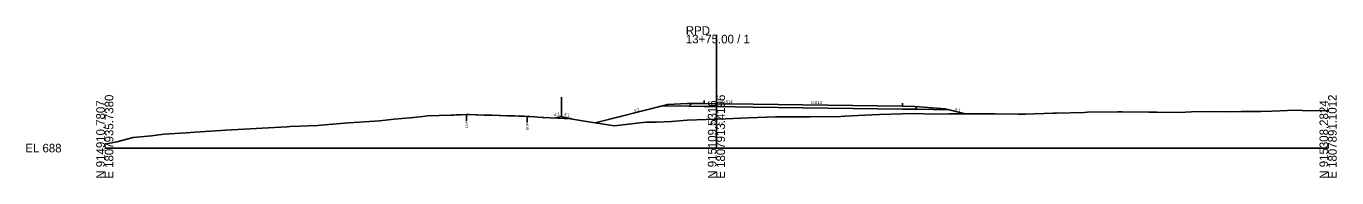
# Model space of a CAD drawing. Extents: x -26 to 403, y -10 to 8517.
# Drawn here: x -25.7 to 402.8, y 7490.3 to 7539.8 of the extents above; entities that cross this region are included whole.
import ezdxf

# ---------------------------------------------------------------- set-up
doc = ezdxf.new("R2010")
doc.units = 0
for name, color, linetype in [('Exist Cross Section Cell', 7, 'Continuous'), ('Exist XS Center Line Elevation Label', 7, 'Continuous'), ('Exist XS Ground Line', 7, 'Continuous'), ('Old_Level_10', 7, 'Continuous'), ('Prop XS Ditch Slope Text', 7, 'Continuous'), ('Prop XS Earthwork Shape', 7, 'Continuous'), ('Prop XS EOT Tick Mark', 7, 'Continuous'), ('Prop XS Finish Grade', 7, 'Continuous'), ('Prop XS Finish Grade Earthwork', 7, 'Continuous'), ('Prop XS Finish Grade Paved Shoulder', 7, 'Continuous'), ('Prop XS Finish Grade Pavement', 7, 'Continuous'), ('Prop XS Hydro Fill Slope Data', 7, 'Continuous'), ('Prop XS Hydro Typical Ditch Data', 7, 'Continuous'), ('Prop XS Pvmt Edge Slope', 7, 'Continuous'), ('Prop XS SE Text', 7, 'Continuous'), ('Prop XS Side Slope Text', 7, 'Continuous'), ('Prop XS Subgrade Earthwork', 7, 'Continuous'), ('Scratch_Level_2', 7, 'Continuous')]:
    doc.layers.add(name, color=color, linetype=linetype)

msp = doc.modelspace()

# ---------------------------------------------------------------- linework, layer by layer
at = {"layer": 'Exist Cross Section Cell'}
for p, q in [((200, 7500), (200, 7537.04)), ((0, 7500), (200, 7500)), ((200, 7500), (400, 7500))]:
    msp.add_line(p, q, dxfattribs=at)
at = {"layer": 'Exist XS Ground Line'}
msp.add_lwpolyline([(0, 7501.27), (3.95, 7502.08), (9.28, 7503.47), (15.28, 7503.99), (19.34, 7504.61), (26.62, 7504.97), (29.4, 7505.2), (37.95, 7505.75), (39.47, 7505.88), (49.53, 7506.45), (51.42, 7506.56), (59.59, 7507), (60.63, 7507.08), (69.65, 7507.42), (71.96, 7507.6), (79.72, 7508.24), (83.3, 7508.49), (89.78, 7508.95), (94.63, 7509.45), (99.84, 7509.87), (104, 7510.33), (105.48, 7510.52), (113.12, 7510.76), (114.08, 7510.82), (114.93, 7510.84), (116.4, 7510.86), (118.24, 7510.96), (119.15, 7510.94), (121.44, 7510.88), (121.85, 7510.86), (123.95, 7510.81), (125.59, 7510.76), (126.57, 7510.72), (128.98, 7510.67), (129.42, 7510.65), (131.5, 7510.59), (133.16, 7510.54), (134.01, 7510.51), (135.42, 7510.47), (136.52, 7510.44), (137.07, 7510.41), (138.16, 7510.38), (138.98, 7510.31), (140.57, 7510.21), (141.56, 7510.14), (143.12, 7510.03), (143.5, 7510.02), (145.68, 7509.93), (148.09, 7509.81), (152.32, 7509.59), (157.54, 7508.74), (166.67, 7507.33), (175, 7508.21), (177.08, 7508.48), (177.56, 7508.43), (180.35, 7508.52), (185.32, 7508.72), (190.41, 7509.1), (196.65, 7509.34), (200, 7509.44), (200.47, 7509.45), (207.99, 7509.75), (210.53, 7509.86), (219.33, 7510.17), (220.6, 7510.21), (230.66, 7510.2), (240.72, 7510.34), (242, 7510.4), (250.79, 7510.92), (253.33, 7510.96), (260.85, 7511.22), (264.67, 7511.29), (270.91, 7511.08), (276.01, 7511.21), (280.97, 7511.24), (287.34, 7511.15), (291.04, 7511.22), (298.68, 7511.1), (301.1, 7511.07), (310.01, 7511.4), (311.16, 7511.41), (320.26, 7511.69), (321.35, 7511.72), (331.29, 7511.85), (332.68, 7511.89), (341.35, 7511.8), (344.02, 7511.76), (351.41, 7511.69), (355.36, 7511.82), (361.48, 7511.92), (366.69, 7511.89), (371.54, 7511.98), (378.03, 7511.97), (381.6, 7512.05), (389.36, 7512.35), (391.67, 7512.33), (400, 7512.19)], dxfattribs=at)
at = {"layer": 'Old_Level_10'}
for p, q in [((118.24, 7510.96), (118.24, 7508.91)), ((138.16, 7510.38), (138.16, 7508.33))]:
    msp.add_line(p, q, dxfattribs=at)
at = {"layer": 'Prop XS Earthwork Shape'}
msp.add_lwpolyline([(276.18, 7512.54), (281.39, 7511.23), (280.97, 7511.24), (276.01, 7511.21), (270.91, 7511.08), (264.67, 7511.29), (260.85, 7511.22), (253.33, 7510.96), (250.79, 7510.92), (242, 7510.4), (240.72, 7510.34), (230.66, 7510.2), (220.6, 7510.21), (219.33, 7510.17), (210.53, 7509.86), (207.99, 7509.75), (200.47, 7509.45), (200, 7509.44), (196.65, 7509.34), (190.41, 7509.1), (185.32, 7508.72), (180.35, 7508.52), (177.56, 7508.43), (177.08, 7508.48), (175, 7508.21), (166.67, 7507.33), (160.39, 7508.3), (182.5, 7513.83), (191.1, 7513.71), (195.98, 7513.64), (199.98, 7513.59), (211.98, 7513.42), (260.82, 7512.75), (265.77, 7512.68)], close=True, dxfattribs=at)
at = {"layer": 'Prop XS EOT Tick Mark'}
for p, q in [((196, 7514.56), (196, 7515.56)), ((260.84, 7513.67), (260.84, 7514.67))]:
    msp.add_line(p, q, dxfattribs=at)
at = {"layer": 'Prop XS Finish Grade'}
for p, q in [((182.5, 7513.83), (184, 7514.2)), ((190.43, 7514.54), (184, 7514.2)), ((192, 7514.61), (190.43, 7514.54)), ((264.84, 7513.61), (266.41, 7513.49)), ((266.41, 7513.49), (274.84, 7512.87)), ((274.84, 7512.87), (276.18, 7512.54))]:
    msp.add_line(p, q, dxfattribs=at)
at = {"layer": 'Prop XS Finish Grade Earthwork'}
for p, q in [((182.5, 7513.83), (160.39, 7508.3)), ((276.18, 7512.54), (281.39, 7511.23)), ((281.36, 7511.24), (281.36, 7511.24))]:
    msp.add_line(p, q, dxfattribs=at)
at = {"layer": 'Prop XS Finish Grade Paved Shoulder'}
for p, q in [((196, 7514.56), (192, 7514.61)), ((260.84, 7513.67), (264.84, 7513.61))]:
    msp.add_line(p, q, dxfattribs=at)
at = {"layer": 'Prop XS Finish Grade Pavement'}
for p, q in [((196, 7514.56), (200, 7514.5)), ((200, 7514.5), (212, 7514.34)), ((212, 7514.34), (260.84, 7513.67))]:
    msp.add_line(p, q, dxfattribs=at)
at = {"layer": 'Prop XS Hydro Fill Slope Data'}
msp.add_line((184, 7514.2), (160.39, 7508.3), dxfattribs=at)
at = {"layer": 'Prop XS Hydro Typical Ditch Data'}
msp.add_line((274.84, 7512.87), (281.36, 7511.24), dxfattribs=at)
at = {"layer": 'Prop XS Pvmt Edge Slope'}
for p, q in [((192, 7514.61), (191.1, 7513.71)), ((264.84, 7513.61), (265.77, 7512.68))]:
    msp.add_line(p, q, dxfattribs=at)
at = {"layer": 'Prop XS Subgrade Earthwork'}
for p, q in [((191.1, 7513.71), (182.5, 7513.83)), ((195.98, 7513.64), (191.1, 7513.71)), ((195.98, 7513.64), (199.98, 7513.59)), ((199.98, 7513.59), (211.98, 7513.42)), ((211.98, 7513.42), (260.82, 7512.75)), ((260.82, 7512.75), (265.77, 7512.68)), ((265.77, 7512.68), (276.18, 7512.54))]:
    msp.add_line(p, q, dxfattribs=at)
at = {"layer": 'Scratch_Level_2'}
for q in [(149.37, 7516.64), (147.33, 7509.85), (152.71, 7509.53)]:
    msp.add_line((149.37, 7510.36), q, dxfattribs=at)

# ---------------------------------------------------------------- texts
at = {"layer": 'Exist Cross Section Cell'}
for s, p in [('RPD', (190, 7537.04)), ('13+75.00 / 1', (190, 7534.24)), ('EL 688', (-26, 7498.6))]:
    msp.add_text(s, height=2.8, dxfattribs=at).set_placement(p)
for s, p in [('E 1807935.7380', (2.8, 7490)), ('E 1807913.4196', (202.8, 7490)), ('E 1807891.1012', (402.8, 7490)), ('N 914910.7807', (0, 7490)), ('N 915109.5316', (200, 7490)), ('N 915308.2824', (400, 7490))]:
    msp.add_text(s, height=2.8, rotation=90, dxfattribs=at).set_placement(p)
at = {"layer": 'Exist XS Center Line Elevation Label'}
msp.add_text('697.44', height=1, dxfattribs=at).set_placement((197.86, 7507.44))
at = {"layer": 'Old_Level_10'}
for p in [(118.63, 7506.51), (138.55, 7505.93)]:
    msp.add_text('EOP', height=0.787, rotation=90, dxfattribs=at).set_placement(p)
at = {"layer": 'Prop XS Ditch Slope Text'}
msp.add_text('4:1', height=1, rotation=345.9638, dxfattribs=at).set_placement((277.82, 7512.28))
at = {"layer": 'Prop XS SE Text'}
for p in [(201.85, 7514.68), (230.99, 7514.44)]:
    msp.add_text('0.014', height=1, rotation=359.2184, dxfattribs=at).set_placement(p)
at = {"layer": 'Prop XS Side Slope Text'}
msp.add_text('4:1', height=1, rotation=14.0362, dxfattribs=at).set_placement((173.14, 7511.72))
at = {"layer": 'Scratch_Level_2'}
for rotation, p in [(14.0362, (147.04, 7510.3)), (345.9638, (150.12, 7510.69))]:
    msp.add_text('4:1', height=1, rotation=rotation, dxfattribs=at).set_placement(p)

doc.saveas('drawing.dxf')
